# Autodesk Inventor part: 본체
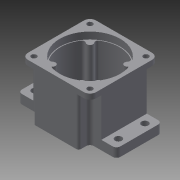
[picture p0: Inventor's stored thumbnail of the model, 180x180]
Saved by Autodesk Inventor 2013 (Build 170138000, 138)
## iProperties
Created: 2015-07
Part Number: 본체
Material: 일반
Document SubType Name: Modeling
Designer: user
Density: 1 g/cm^3
Author: user
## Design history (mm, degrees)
node "작업 평면2"
  node "작업 평면1"
sketch "스케치3"
  geometry: L1 (0, -45)-(0, 45); L2 (27, -45)-(-27, -45); L3 (27, 45)-(-27, 45); L4 (65, 0)-(-65, 0); L5 (65, 25)-(65, -25); L6 (-65, 25)-(-65, -25); L7 (60, 30)-(35, 30); L8 (30, 35)-(30, 42); L9 (-30, 42)-(-30, 35); L10 (-35, 30)-(-60, 30); L11 (-60, -30)-(-35, -30); L12 (-30, -35)-(-30, -42); L13 (30, -42)-(30, -35); L14 (35, -30)-(60, -30); L15 (65, 17.5)-(-65, 17.5); L16 (65, -17.5)-(-65, -17.5); L17 (55, 22.274)-(55, -21.704); L18 (-55, 21.508)-(-55, -21.704); C1 r 4.5 at (-55, 17.5); C2 r 4.5 at (-55, -17.5); C3 r 4.5 at (55, -17.5); C4 r 4.5 at (55, 17.5); A1 r 5 centre (35, 35) between (30, 35) and (35, 30); A2 r 5 centre (-35, 35) between (-35, 30) and (-30, 35); A3 r 5 centre (-35, -35) between (-30, -35) and (-35, -30); A4 r 5 centre (35, -35) between (35, -30) and (30, -35); A5 r 5 centre (60, 25) between (65, 25) and (60, 30); A6 r 5 centre (60, -25) between (60, -30) and (65, -25); A7 r 5 centre (-60, -25) between (-65, -25) and (-60, -30); A8 r 5 centre (-60, 25) between (-60, 30) and (-65, 25); A9 r 3 centre (27, 42) between (30, 42) and (27, 45); A10 r 3 centre (-27, 42) between (-27, 45) and (-30, 42); A11 r 3 centre (27, -42) between (27, -45) and (30, -42); A12 r 3 centre (-27, -42) between (-30, -42) and (-27, -45); 8 further points
  constraints: 36 end point, 25 tangent, 24 point on circle, 20 point on line, 16 centre point, 9 equal radius, 9 parallel, 8 perpendicular, 6 midpoint, 1 coincident, 1 vertical
  dimensions: "d9" = 90 distance of L1.start L1.end; "d10" = 60 distance of point (30, -45) point (-30, -45); "d12" = 130 distance of L4.end L4.start; "d13" = 60 distance of point (65, 30) point (65, -30); "d14" = 60 distance of point (-65, 30) point (-65, -30); "d15" = 5 radius of A1; "d16" = 5 radius of A5; "d17" = 17.5 distance between parallel lines of L15 L4; "d18" = 17.5 distance between parallel lines of L16 L4; "d19" = 10 distance between parallel lines of L17 L5; "d20" = 10 distance between parallel lines of L6 L18; "d21" = 9 diameter of C1; "d22" = 9 diameter of C2; "d23" = 9 diameter of C3; "d24" = 9 diameter of C4; "d25" = 0 distance from line of L15.start L5; "d26" = 0 distance from line of L16.start L5; "d27" = 7.72623 distance from line of L17.start L7; "d28" = 51.70361 distance from line of L17.end L7; "d29" = 8.49239 distance from line of L18.start L7; "d30" = 51.70361 distance from line of L18.end L7; "d31" = 130 distance from line of L15.end L5; "d32" = 130 distance from line of L16.end L5; "d33" = 3 radius of A9
extrude "돌출3" join sketch "스케치3" distance "d34" = 12; taper "d35" = 0 deg
sketch "스케치4"
  geometry: L1 (27, -45)-(-27, -45) reference; L2 (30, 42)-(30, 35) reference; L3 (0, -45)-(0, -30); L4 (-24.063, -26.429)-(24.063, -26.429); L5 (24.063, -26.429)-(24.063, -33.571); L6 (24.063, -33.571)-(-24.063, -33.571); L7 (-24.063, -33.571)-(-24.063, -26.429); L8 (0, -26.429)-(0, -33.571); 2 further points
  constraints: 4 end point, 4 midpoint, 2 coincident, 1 parallel, 2 other
  dimensions: "d36" = 15 distance of L3.start L3.end
feature "엠보싱1" sketch "스케치4" dims "d9" = 90, "d10" = 60, "d12" = 130, "d13" = 60, "d14" = 60, "d15" = 5, "d16" = 5, "d17" = 17.5, "d18" = 17.5, "d19" = 10, "d20" = 10, "d21" = 9, "d22" = 9, "d23" = 9, "d24" = 9, "d25" = 0, "d26" = 0, "d27" = 7.72623, "d28" = 51.70361, "d29" = 8.49239, "d30" = 51.70361, "d31" = 130, "d32" = 130, "d33" = 3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
sketch "스케치5"
  geometry: L1 (-27, -45)-(27, -45) reference; L2 (30, -42)-(30, -35) reference; L3 (35, -30)-(60, -30) reference; L4 (60, 30)-(35, 30) reference; L5 (30, 35)-(30, 42) reference; L6 (-30, 42)-(-30, 35) reference; L7 (-35, 30)-(-60, 30) reference; L8 (-60, -30)-(-35, -30) reference; L9 (-30, -35)-(-30, -42) reference; L10 (-27, 45)-(27, 45); L11 (45, 45)-(45, -30); L12 (45, -45)-(-45, -45); L13 (-45, -30)-(-45, 30); L14 (0, 45)-(0, -45); L15 (45, 30)-(35, 30); L16 (45, 30)-(45, -30); A1 r 3 centre (27, -42) between (27, -45) and (30, -42) reference; A2 r 5 centre (35, -35) between (35, -30) and (30, -35) reference; A3 r 5 centre (35, 35) between (30, 35) and (35, 30) reference; A4 r 3 centre (27, 42) between (30, 42) and (27, 45) reference; A5 r 3 centre (-27, 42) between (-27, 45) and (-30, 42) reference; A6 r 5 centre (-35, 35) between (-35, 30) and (-30, 35) reference; A7 r 5 centre (-35, -35) between (-30, -35) and (-35, -30) reference; A8 r 3 centre (-27, -42) between (-30, -42) and (-27, -45) reference; 2 further points
  constraints: 14 end point, 5 point on line, 3 midpoint, 2 parallel, 2 perpendicular, 2 point on circle, 1 coincident, 1 collinear, 1 horizontal, 1 tangent
  dimensions: "d39" = 90 distance of L12.start L12.end; "d40" = 90 distance of L11.start L12.start
extrude "돌출4" join sketch "스케치5" distance "d41" = 51; taper "d42" = 0 deg
sketch "스케치6"
  geometry: L1 (-45, 45)-(45, 45); L2 (45, 45)-(45, -45); L3 (45, -45)-(-45, -45); L4 (-45, -45)-(-45, 45); L5 (0, 45)-(0, -45); L6 (0, 37)-(0, -37); C1 r 3.5 at (-37, 37); C2 r 3.5 at (37, 37); C3 r 3.5 at (37, -37); C4 r 3.5 at (-37, -37); 2 further points
  constraints: 12 end point, 4 centre point, 4 midpoint, 2 parallel, 1 coincident, 1 horizontal, 1 perpendicular
  dimensions: "d43" = 90 distance of L2.end L3.end; "d44" = 90 distance of L1.end L2.end; "d47" = 7 diameter of C1; "d48" = 7 diameter of C2; "d49" = 7 diameter of C3; "d50" = 7 diameter of C4
extrude "돌출5" join sketch "스케치6" distance "d51" = 7; taper "d52" = 0 deg
fillet "모깎기1" dims "d53" = 8
sketch "스케치7"
  geometry: L1 (-45, 37)-(-45, -37) reference; L2 (-37, -45)-(37, -45) reference; L3 (45, -37)-(45, 37) reference; L4 (37, 45)-(-37, 45) reference; L5 (-40, 0)-(40, 0); C1 r 3.5 at (37, 37) reference; C2 r 3.5 at (37, -37) reference; C3 r 3.5 at (-37, -37) reference; C4 r 3.5 at (-37, 37) reference; A1 r 8 centre (-37, 37) between (-37, 45) and (-45, 37) reference; A2 r 8 centre (-37, -37) between (-45, -37) and (-37, -45) reference; A3 r 8 centre (37, -37) between (37, -45) and (45, -37) reference; A4 r 8 centre (37, 37) between (45, 37) and (37, 45) reference; A5 r 40 centre (0, 0) between (-40, 0) and (40, 0); 1 further point
  constraints: 2 end point, 2 point on circle, 1 centre point, 1 coincident, 1 parallel
  dimensions: "d54" = 80 diameter of A5
sketch "스케치8"
  geometry: L1 (65, 25)-(65, -25) reference; L2 (-45.213, 0)-(65, 0); L3 (-45.213, 11)-(48.981, 11); L4 (0, 0)-(0, 11); C1 r 25 at (0, 11)
  constraints: 6 end point, 1 centre point, 1 coincident, 1 midpoint, 1 parallel, 1 perpendicular, 1 point on line
  dimensions: "d55" = 11 distance between parallel lines of L2 L3; "d57" = 50 diameter of C1
extrude "돌출6" join sketch "스케치8" distance "d58" = 7; taper "d59" = 0 deg
fillet "모깎기2" dims "d60" = 3
fillet "모깎기3" dims "d61" = 3
sketch "스케치9"
  geometry: C1 r 22 at (0, 0) reference; C2 r 16 at (0, 0); 1 further point
  constraints: 1 centre point, 1 coincident
  dimensions: "d62" = 32 diameter of C2
extrude "돌출7" cut sketch "스케치9" distance "d63" = 8; taper "d64" = 0 deg
chamfer "모따기1" distance "d65" = 1; stored, may be unused: second distance "d66" = 2, angle "d67" = 45 deg
sketch "스케치10"
  geometry: C1 r 16 at (0, 0) reference; C2 r 12.5 at (0, 0); 1 further point
  constraints: 1 centre point, 1 coincident
  dimensions: "d68" = 25 diameter of C2
extrude "돌출8" cut sketch "스케치10" distance "d69" = 5; taper "d70" = 0 deg
fillet "모깎기4" dims "d71" = 0.3
sketch "스케치11"
  geometry: C1 r 12.5 at (0, 0) reference; C2 r 17.5 at (0, 0); 1 further point
  constraints: 1 centre point, 1 coincident
  dimensions: "d72" = 35 diameter of C2
extrude "돌출9" cut sketch "스케치11" distance "d73" = 10; taper "d74" = 0 deg
sketch "스케치12"
  geometry: L1 (-45, 37)-(-45, -37) reference; L2 (-37, -45)-(37, -45) reference; L3 (45, -37)-(45, 37) reference; L4 (37, 45)-(-37, 45) reference; C1 r 3.5 at (37, 37) reference; C2 r 3.5 at (37, -37) reference; C3 r 3.5 at (-37, -37) reference; C4 r 3.5 at (-37, 37) reference; A1 r 8 centre (-37, 37) between (-37, 45) and (-45, 37) reference; A2 r 8 centre (-37, -37) between (-45, -37) and (-37, -45) reference; A3 r 8 centre (37, -37) between (37, -45) and (45, -37) reference; A4 r 8 centre (37, 37) between (45, 37) and (37, 45) reference; 1 further point
sketch "스케치13"
  geometry: C1 r 40 at (0, 0); 1 further point
  constraints: 1 centre point, 1 coincident
  dimensions: "d75" = 80 diameter of C1
extrude "돌출10" cut sketch "스케치13" distance "d76" = 9; taper "d77" = 0 deg
sketch "스케치14"
  geometry: L1 (-24.749, 24.749)-(45.251, 24.749); L2 (-6.439, 24.749)-(63.561, 24.749); L3 (24.749, 24.749)-(94.749, 24.749); C1 r 40 at (0, 0) reference; C2 r 39 at (0, 0); 2 further points
  constraints: 6 end point, 3 horizontal, 2 coincident, 1 centre point, 1 point on line
  dimensions: "d91" = 78 diameter of C2
extrude "돌출11" cut sketch "스케치14" distance "d93" = 45; taper "d94" = 0 deg
chamfer "모따기2" distance "d95" = 1; stored, may be unused: second distance "d96" = 2, angle "d97" = 45 deg
sketch "스케치15"
  geometry: L1 (0, 0)-(0, -20); C1 r 39 at (0, 0) reference; C2 r 11 at (0, -20)
  constraints: 2 end point, 1 centre point, 1 coincident, 1 vertical
  dimensions: "d98" = 20 distance of L1.start L1.end; "d99" = 22 diameter of C2
extrude "돌출12" cut sketch "스케치15" distance "d100" = 7; taper "d101" = 0 deg
sketch "스케치16"
  geometry: C1 r 11 at (0, 0) reference; C2 r 9.5 at (0, 0); 1 further point
  constraints: 1 centre point, 1 coincident
  dimensions: "d102" = 19 diameter of C2
extrude "돌출13" cut sketch "스케치16" distance "d103" = 1; taper "d104" = 0 deg
fillet "모깎기5" dims "d105" = 3
fillet "모깎기6" dims "d106" = 0.3
chamfer "모따기3" distance "d107" = 1; stored, may be unused: second distance "d108" = 2, angle "d109" = 45 deg
node "작업 평면4"
sketch "스케치17"
  geometry: L1 (23.82, 72.428)-(73.317, 121.926); L2 (23.82, 72.428)-(93.82, 72.428); C1 r 39 at (0, 0); C2 r 35 at (0, 0); 1 further point
  constraints: 4 end point, 2 centre point, 2 coincident, 1 equal length, 1 horizontal
  dimensions: "d110" = 78 diameter of C1; "d111" = 70 diameter of C2; "d112" = 70 distance of L1.start L1.end; "d113" = 45 deg angle of L2 L1
sketch "스케치18"
  geometry: L1 (-24.749, 24.749)-(45.251, 24.749); L2 (24.749, 24.749)-(-24.749, -24.749); L3 (24.749, 24.749)-(94.749, 24.749); C1 r 39 at (0, 0) reference; C2 r 40 at (0, 0) reference; A1 r 39 centre (0, 0) between (-21.134, 32.777) and (-32.777, 21.134); A2 r 4 centre (-24.749, 24.749) between (-27.462, 21.809) and (-21.809, 27.462); A3 r 3.5 centre (-19.238, 29.836) between (-21.134, 32.777) and (-21.762, 27.412); A4 r 3.5 centre (-29.836, 19.238) between (-27.412, 21.762) and (-32.777, 21.134); 2 further points
  constraints: 10 point on circle, 6 end point, 5 tangent, 4 centre point, 3 coincident, 2 horizontal, 1 equal length, 1 midpoint
  dimensions: "d114" = 78 diameter of A1; "d118" = 70 distance of L2.start L2.end; "d119" = 135 deg angle of L2 L3 (derived); "d120" = 8 diameter of A2; "d122" = 7 diameter of A3; "d124" = 7 diameter of A4; "d125" = 24.74874 distance from line of C2.centre L1; "d126" = 2.66297 distance from line of A3.end L1; "d127" = 2.98642 distance from line of A4.start L1; "d128" = 51.5769 distance of L1.end C2.centre
extrude "돌출14" join sketch "스케치18" distance "d129" = 45; taper "d130" = 0 deg
node "솔리드1"
pattern_circular "원형 패턴1" dims angle "d132" = 360 deg
other parameters: "d7" = 12
